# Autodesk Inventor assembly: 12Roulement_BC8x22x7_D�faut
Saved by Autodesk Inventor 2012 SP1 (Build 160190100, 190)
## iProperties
Created: 2011-01
Part Number: 12Roulement_BC8x22x7_D�faut
Document SubType Name: Assembly
Designer: eric
Mass: 1.54909 g
Surface Area: 21.7227 cm^2
Volume: 1.54909 cm^3
Density: 1 g/cm^3
Author: eric
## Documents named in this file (4)
- D:\Cours\Inventor salle SI\chariot_de_golf_2008\chariot_de_golf_trolem\12Roulement_BC8x22x7_Defaut.iam
- D:\Cours\Inventor salle SI\chariot_de_golf_2008\chariot_de_golf_trolem\Roulement_r1rb_Bint16_Defaut.ipt
- D:\Cours\Inventor salle SI\chariot_de_golf_2008\chariot_de_golf_trolem\Roulement_r1rb_Eroul16_Defaut.ipt
- D:\Cours\Inventor salle SI\chariot_de_golf_2008\chariot_de_golf_trolem\Roulement_r1rb_Bext16_Defaut.ipt
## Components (10 placed, 3 different names)
1. Roulement_r1rb_Bint16_Defaut:1
2. Roulement_r1rb_Eroul16_Defaut:1
3. Roulement_r1rb_Eroul16_Defaut:2
4. Roulement_r1rb_Eroul16_Defaut:3
5. Roulement_r1rb_Eroul16_Defaut:4
6. Roulement_r1rb_Eroul16_Defaut:5
7. Roulement_r1rb_Eroul16_Defaut:6
8. Roulement_r1rb_Eroul16_Defaut:7
9. Roulement_r1rb_Bext16_Defaut:1
10. Roulement_r1rb_Eroul16_Defaut:8
